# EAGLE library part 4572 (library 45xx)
INVERTER/OR/NOR (MC14572BCP)
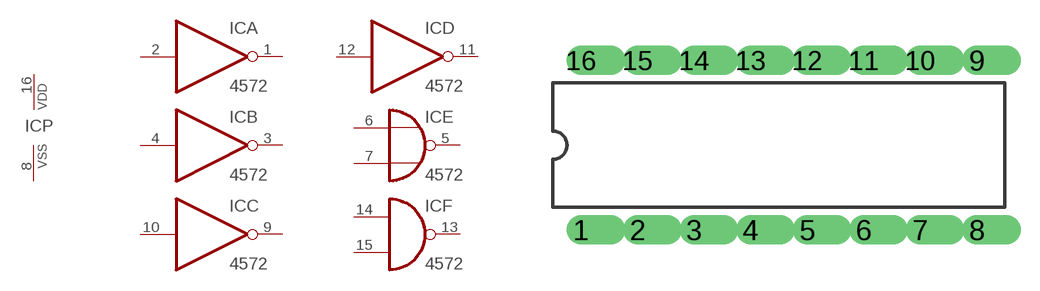
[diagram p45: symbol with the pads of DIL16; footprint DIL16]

Designator prefix IC; gates P=PWRN A=4572 B=4572 C=4572 D=4572 E=4572/A F=4572/B

## 4572N  [DIL16]
1  A:O  out
2  A:I  in
3  B:O  out
4  B:I  in
5  E:O  out
6  E:I0  in
7  E:I1  in
8  P:VSS  pwr
9  C:O  out
10  C:I  in
11  D:O  out
12  D:I  in
13  F:O  out
14  F:I0  in
15  F:I1  in
16  P:VDD  pwr

## Footprint DIL16 (pad centres in mm)
Dual In Line
drill 0.813 offset: 1 -8.89,-3.81; 2 -6.35,-3.81; 3 -3.81,-3.81; 4 -1.27,-3.81; 5 1.27,-3.81; 6 3.81,-3.81; 7 6.35,-3.81; 8 8.89,-3.81; 9 8.89,3.81; 10 6.35,3.81; 11 3.81,3.81; 12 1.27,3.81; 13 -1.27,3.81; 14 -3.81,3.81; 15 -6.35,3.81; 16 -8.89,3.81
